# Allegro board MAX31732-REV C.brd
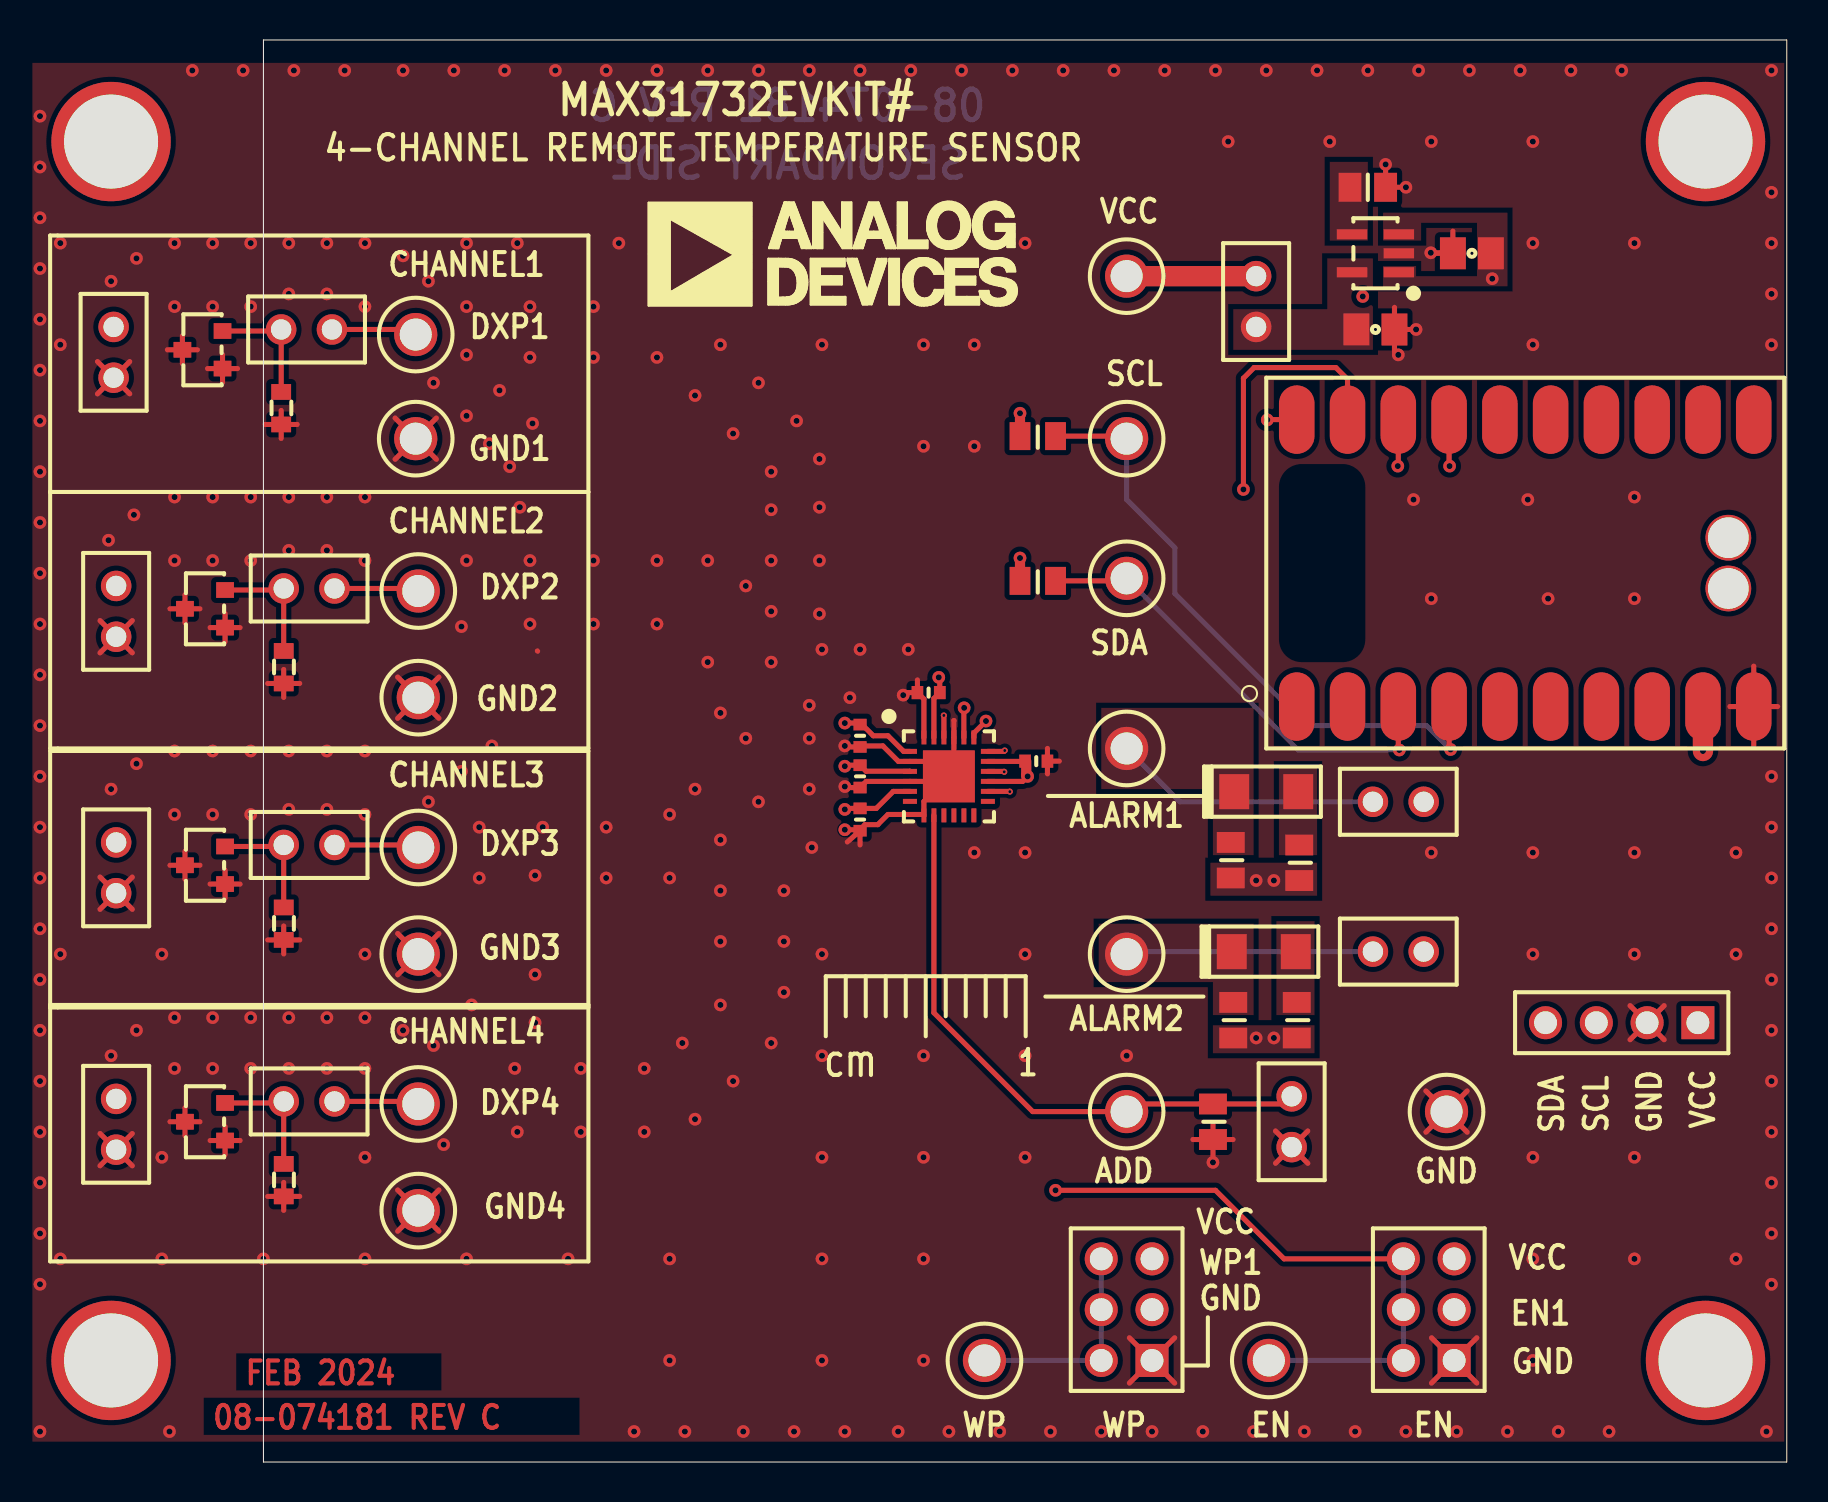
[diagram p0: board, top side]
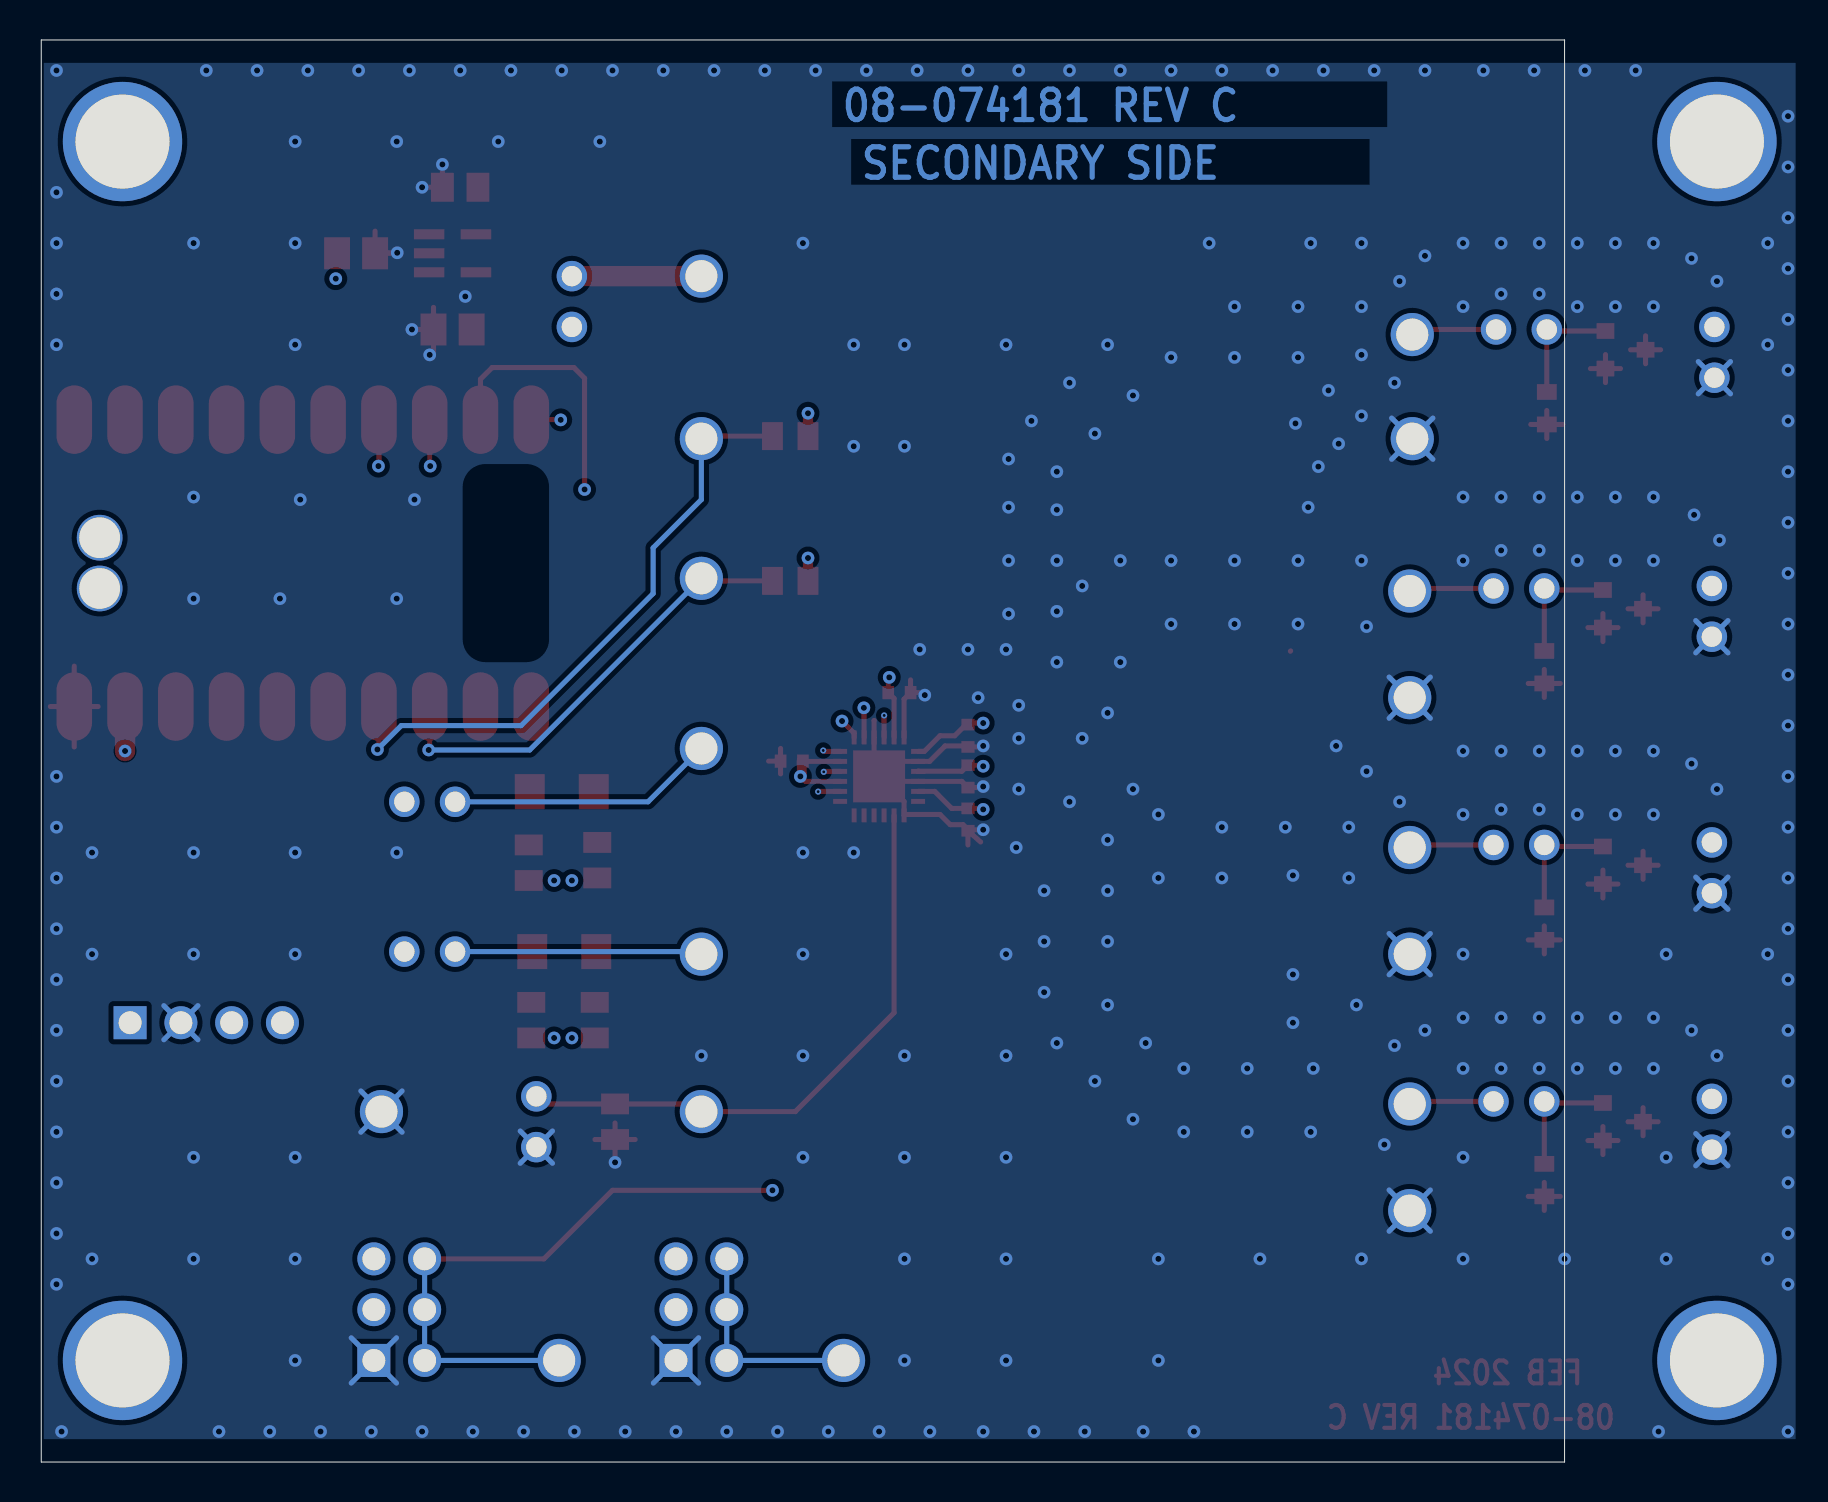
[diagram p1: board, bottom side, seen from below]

Outline 76.2 x 71.12 mm; copper layers: TOP, LAYER_2, LAYER_3, BOTTOM. Coordinates in mm from the lower left corner of the outline.
Outline path: 0,71.12 0,0 76.2,0 76.2,71.12 0,71.12

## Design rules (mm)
constraint set DEFAULT: min track width 0.254

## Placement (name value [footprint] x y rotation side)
C1A  100PF  [C0402]  33.27 38.48 180 top
C1B  100PF  [C0402]  29.85 36.32 270 top
C1C  100PF  [C0402]  29.85 34.29 270 top
C1D  100PF  [C0402]  29.85 32.13 270 top
C2A  TBD0603  [C0603]  0.89 52.7 270 top
C2B  TBD0603  [C0603]  1.02 39.75 270 top
C2C  TBD0603  [C0603]  1.02 26.92 270 top
C2D  TBD0603  [C0603]  1.02 14.1 270 top
C3  0.1uF  [C0402]  38.66 35.05 0 top
C4  0.1UF  [C0805]  55.24 63.75 0 top
C5  1uF  [C0805H60]  60.45 60.45 180 top
C6  1uF  [C0805H60]  55.63 56.64 0 top
DS1  SML-LX1206IW-TR  [LEDSML126W63H43]  50.17 33.53 0 top
DS2  SML-LX1206IW-TR  [LEDSML126W63H43]  50.04 25.53 0 top
H1  PREC004SAAN-RC  [CNTHMHDR1X4L400W100H336]  71.75 21.97 180 top
J1  PEC02SAAN  [CNSULLINSPEC02SAAN]  3.43 56.64 180 top
J2  PEC02SAAN  [CNSULLINSPEC02SAAN]  3.56 43.69 180 top
J3  PEC02SAAN  [CNSULLINSPEC02SAAN]  3.56 30.86 180 top
J4  PEC02SAAN  [CNSULLINSPEC02SAAN]  3.56 18.03 180 top
J5  PEC02SAAN  [CNSULLINSPEC02SAAN]  49.66 59.31 270 top
J6  PEC02SAAN  [CNSULLINSPEC02SAAN]  51.44 18.29 270 top
J7  TSW-103-07-F-D  [CNSAMTEC2X3H330LD36]  44.45 5.08 90 top
J8  TSW-103-07-F-D  [CNSAMTEC2X3H330LD36]  59.56 5.08 90 top
J9  PEC02SAAN  [CNSULLINSPEC02SAAN]  55.5 33.02 0 top
J10  PEC02SAAN  [CNSULLINSPEC02SAAN]  55.5 25.53 0 top
J11  PEC02SAAN  [CNSULLINSPEC02SAAN]  -7.49 56.77 270 top
J12  PEC02SAAN  [CNSULLINSPEC02SAAN]  -7.37 43.81 270 top
J13  PEC02SAAN  [CNSULLINSPEC02SAAN]  -7.37 30.99 270 top
J14  PEC02SAAN  [CNSULLINSPEC02SAAN]  -7.37 18.16 270 top
NOREF  -  []  -12.7 0 90 top
NOREF#2  -  []  275.21 77.85 0 top
NOREF#3  -  []  -60.71 -173.48 0 top
NOREF#4  -  [unnamed#2]  -7.62 5.08 0 top
NOREF#5  -  []  48.69 71.12 0 top
NOREF#6  -  []  76.58 70.48 180 top
NOREF#7  -  []  30.04 19.34 0 top
NOREF#8  -  []  -102.74 -190.75 0 top
NOREF#9  -  []  0.64 70.48 270 top
NOREF#10  -  []  77.22 49.53 0 top
NOREF#11  -  []  343.12 241.69 0 top
NOREF#12  -  []  0.64 0.64 0 top
NOREF#13  -  [unnamed#2]  -7.62 66.04 0 top
NOREF#14  -  []  -12.7 71.12 0 top
NOREF#15  -  []  76.58 0.64 90 top
NOREF#16  -  []  54.99 49.49 0 top
NOREF#17  -  [unnamed#2]  72.14 66.04 0 top
NOREF#18  -  []  37.08 90.21 0 top
NOREF#19  -  []  48.57 49.78 0 top
NOREF#20  -  []  178.18 232.41 0 top
NOREF#21  -  [unnamed#2]  72.14 5.08 0 top
NOREF#22  -  []  350.14 178.18 0 top
Q1  MMBT3906-7-F  [SOT23-M3]  -3.05 55.63 90 top
Q2  MMBT3906-7-F  [SOT23-M3]  -2.92 42.67 90 top
Q3  MMBT3906-7-F  [SOT23-M3]  -2.92 29.84 90 top
Q4  MMBT3906-7-F  [SOT23-M3]  -2.92 17.02 90 top
R1  4.7K  [R0805]  38.73 51.31 180 top
R2  4.7K  [R0805]  38.73 44.07 180 top
R3  15K  [R0805]  47.5 17.02 270 top
R4  4.7K  [R0805]  48.39 30.1 270 top
R5  330  [R0805]  51.82 29.97 270 top
R6  4.7K  [R0805]  48.51 22.1 270 top
R7  330  [R0805]  51.69 22.1 270 top
TP1  WHT  [CNKEY5005-9TP]  7.62 56.39 0 top
TP2  WHT  [CNKEY5005-9TP]  7.62 51.18 0 top
TP3  WHT  [CNKEY5005-9TP]  7.75 43.56 0 top
TP4  WHT  [CNKEY5005-9TP]  7.75 38.23 0 top
TP5  WHT  [CNKEY5005-9TP]  7.75 30.73 0 top
TP6  WHT  [CNKEY5005-9TP]  7.75 25.4 0 top
TP7  WHT  [CNKEY5005-9TP]  7.75 17.91 0 top
TP8  WHT  [CNKEY5005-9TP]  7.75 12.57 0 top
TP9  RED  [CNKEY5005-9TP]  43.18 59.31 0 top
TP10  WHT  [CNKEY5005-9TP]  36.07 5.08 0 top
TP11  WHT  [CNKEY5005-9TP]  50.29 5.08 0 top
TP12  WHT  [CNKEY5005-9TP]  43.18 51.18 0 top
TP13  WHT  [CNKEY5005-9TP]  43.18 44.2 0 top
TP14  WHT  [CNKEY5005-9TP]  43.18 17.53 0 top
TP15  WHT  [CNKEY5005-9TP]  43.18 35.69 0 top
TP16  WHT  [CNKEY5005-9TP]  43.18 25.4 0 top
TP19  BLK  [CNKEY5005-9TP]  59.18 17.53 0 top
U1  MAX31732ATG+  [QFN24_90-0022]  34.29 34.29 270 top
U2  MAX32625PICO#  [MMAX32625PICO_SOCKETED]  63.12 44.96 90 top
U3  LTC1844ES5-3.3#TRMPBF  [TSOT-5]  55.63 60.45 90 top

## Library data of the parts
C1A C1B C1C C1D = CAP: Tolerance: 10; User Part Number: UPN; alternate symbols: (C0402); part number: CAP_SM-100PF,16V,10,E042886,C0402; tolerance: 10
C2A C2B C2C C2D = CAP: User Part Number: UPN; alternate symbols: (C0603); part number: CAP_SM-TBD0603,TBD0603,TBD0603,E000382,C0603
C3 = CAP: Tolerance: 10; User Part Number: UPN; alternate symbols: (C0402); part number: CAP_SM-0.1UF,25V,10,E025751,C0402; tolerance: 10
C4 = CAP: Tolerance: 10; User Part Number: UPN; alternate symbols: (C0805); part number: CAP_SM-0.1UF,25V,10,E059709,C0805; tolerance: 10
C5 C6 = CAP: Tolerance: 10; User Part Number: UPN; alternate symbols: (C0805H60); part number: CAP_SM-1UF,25V,10,E007664,C0805H60; tolerance: 10
DS1 DS2 = DIOLED: Tolerance: N/A; User Part Number: UPN; alternate symbols: (LEDSML126W63H43); part number: DIOLED_SM-SML-LX1206IW-TR,N/A,N/A,E008005,LEDSML126W63H43; tolerance: N/A
H1 = CN4P: User Part Number: UPN; Tolerance: N/A; alternate symbols: (CNTHMHDR1X4L400W100H336); part number: CN4P_TH-PREC004SAAN-RC,E030958,CNTHMHDR1X4L400W100H336; tolerance: N/A
J1-J6 J9-J14 = CN2P: Tolerance: N/A; User Part Number: UPN; alternate symbols: (CNSULLINSPEC02SAAN); part number: CN2P_TH-PEC02SAAN,E011286,CNSULLINSPEC02SAAN; tolerance: N/A
J7 J8 = CN6P_ODD_EVEN: Tolerance: N/A; User Part Number: UPN; alternate symbols: (CNSAMTEC2X3H330LD36); part number: CN6P_ODD_EVEN_TH-TSW-103-07-F-D,E031502,CNSAMTEC2X3H330LD36; tolerance: N/A
Q1-Q4 = TRANPNP_V3: User Part Number: UPN; Tolerance: N/A; alternate symbols: (SOT23-M3); part number: TRANPNP_V3_SM-MMBT3906-7-F,E034958,SOT23-M3; tolerance: N/A
R1 R2 R4 R6 = RES: Tolerance: 0.1; User Part Number: UPN; alternate symbols: (R0805); part number: RES_SM-4.7K,E034780,1/4W,0.1,R0805; tolerance: 0.1
R3 = RES: Tolerance: 0.1; User Part Number: UPN; alternate symbols: (R0805); part number: RES_SM-15K,E003804,1/8W,0.1,R0805; tolerance: 0.1
R5 R7 = RES: Tolerance: 0.1; User Part Number: UPN; alternate symbols: (R0805); part number: RES_SM-330,E025081,1/8W,0.1,R0805; tolerance: 0.1
TP1-TP8 TP10-TP16 = CNTP1P: Tolerance: N/A; User Part Number: UPN; alternate symbols: (CNKEY5005-9TP); part number: CNTP1P_TH-WHT,E025331,CNKEY5005-9TP; tolerance: N/A
TP9 = CNTP1P: Tolerance: N/A; User Part Number: UPN; alternate symbols: (CNKEY5005-9TP); part number: CNTP1P_TH-RED,E019607,CNKEY5005-9TP; tolerance: N/A
TP19 = CNTP1P: Tolerance: N/A; User Part Number: UPN; alternate symbols: (CNKEY5005-9TP); part number: CNTP1P_TH-BLK,E015367,CNKEY5005-9TP; tolerance: N/A
U1 = ADMAX31732_V2: User Part Number: UPN; Tolerance: N/A; alternate symbols: (QFN24_90-0022); part number: ADMAX31732_V2_SM-MAX31732ATG+,E060544,QFN24_90-0022; tolerance: N/A
U2 = MOD_MAX32625: User Part Number: UPN; Tolerance: N/A; alternate symbols: (MODMAX32625PICO_20P); part number: MOD_MAX32625_TH-MAX32625PICO#,E060564,MMAX32625PICO_SOCKETED; tolerance: N/A
U3 = LINLTC1844: User Part Number: UPN; Tolerance: N/A; alternate symbols: (TSOT-5); part number: LINLTC1844_SM-LTC1844ES5-3.3#TRMPBF,E034094,TSOT-5; tolerance: N/A

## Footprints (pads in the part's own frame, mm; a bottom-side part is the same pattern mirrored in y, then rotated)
C0402
  rect 0.584x0.66 smd: 1(-0.559,0) 2(0.559,0)
C0603
  rect 0.787x0.991 smd: 1(-0.813,0) 2(0.813,0)
C0805
  rect 1.143x1.448 smd: 1(-0.889,0) 2(0.889,0)
C0805H60
  rect 1.295x1.6 smd: 1(-0.953,0) 2(0.953,0)
CNKEY5005-9TP
  round 2.159 hole 1.6: 1(0,0)
CNSAMTEC2X3H330LD36
  rect 1.651x1.651 hole 1.143: 1(0,0)
  round 1.651 hole 1.143: 2(0,2.54) 3(2.54,0) 4(2.54,2.54) 5(5.08,0) 6(5.08,2.54)
CNSULLINSPEC02SAAN
  round 1.524 hole 1.016: 1(0,0) 2(2.54,0)
CNTHMHDR1X4L400W100H336
  rect 1.651x1.651 hole 1.143: 1(0,0)
  round 1.651 hole 1.143: 2(2.54,0) 3(5.08,0) 4(7.62,0)
LEDSML126W63H43
  rect 1.499x1.753 smd: A(1.6,0) C(-1.6,0)
MMAX32625PICO_SOCKETED
  round 2.286 hole 2.032 unplated: (-1.27,-10.16) (1.27,-10.16)
  rrect 3.429x1.778 smd: 1(-7.176,11.43) 2(-7.176,8.89) 3(-7.176,6.35) 4(-7.176,3.81) 5(-7.176,1.27) 6(-7.176,-1.27) 7(-7.176,-3.81) 8(-7.176,-6.35) 9(-7.176,-8.89) 10(-7.176,-11.43) 11(7.176,-11.43) 12(7.176,-8.89) 13(7.176,-6.35) 14(7.176,-3.81) 15(7.176,-1.27) 16(7.176,1.27) 17(7.176,3.81) 18(7.176,6.35) 19(7.176,8.89) 20(7.176,11.43)
QFN24_90-0022
  rect 0.25x0.7 smd: 1(-1.25,-1.95) 2(-0.75,-1.95) 3(-0.25,-1.95) 4(0.25,-1.95) 5(0.75,-1.95) 6(1.25,-1.95) 13(1.25,1.95) 14(0.75,1.95) 15(0.25,1.95) 16(-0.25,1.95) 17(-0.75,1.95) 18(-1.25,1.95)
  rect 0.7x0.25 smd: 7(1.95,-1.25) 8(1.95,-0.75) 9(1.95,-0.25) 10(1.95,0.25) 11(1.95,0.75) 12(1.95,1.25) 19(-1.95,1.25) 20(-1.95,0.75) 21(-1.95,0.25) 22(-1.95,-0.25) 23(-1.95,-0.75) 24(-1.95,-1.25)
  rect 2.6x2.6 smd: 25(0,0)
R0805
  rect 1.041x1.397 smd: 1(-0.889,0) 2(0.889,0)
SOT23-M3
  rect 0.787x0.889 smd: 1(-0.94,-1.003) 2(0.94,-1.003) 3(0,1.003)
TSOT-5
  rect 0.508x1.524 smd: 1(-0.95,-1.17) 2(0,-1.17) 3(0.95,-1.17) 4(0.95,1.17) 5(-0.95,1.17)
unnamed#2
  round 5.969 hole 4.699 unplated: (0,0)

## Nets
3.3V: C6.1 J5.2(N2) U3.5
+5V: C5.1 U2.9 U3.1 U3.3(SHDN_N)
GND_SIGNAL: C1A.2(N2) C1B.2(N2) C1C.2(N2) C1D.2(N2) C2A.2(N2) C2B.2(N2) C2C.2(N2) C2D.2(N2) C3.2(N2) C4.2(N2) C5.2(N2) C6.2(N2) H1.2 J6.2(N2) J7.1 J8.1 J11.2(N2) J12.2(N2) J13.2(N2) J14.2(N2) Q1.1 Q1.3 Q2.1 Q2.3 Q3.1 Q3.3 Q4.1 Q4.3 R3.2(N2) TP2.1(N1) TP4.1(N1) TP6.1(N1) TP8.1(N1) TP19.1(N1) U1.2 U1.4 U1.7 U1.21 U1.24 U1.25 U2.10 U3.2
VCC: C3.1 H1.1 J5.1 J7.5 J8.5 R1.2(N2) R2.2(N2) R4.2(N2) R5.2(N2) R6.2(N2) R7.2(N2) TP9.1(N1) U1.15 U1.17
ADD: J6.1 R3.1 TP14.1(N1) U1.8
AL1: J9.2(N2) U2.18
AL2: J10.2(N2) U2.17
DXP1: C1A.1 J1.1 J11.1 TP1.1(N1) U1.23
DXP2: C1B.1 J2.1 J12.1 TP3.1(N1) U1.1
DXP3: C1C.1 J3.1 J13.1 TP5.1(N1) U1.3
DXP4: C1D.1 J4.1 J14.1 TP7.1(N1) U1.5
EN: J8.2 J8.4 J8.6(N6) TP11.1(N1) U1.14
EN1: J8.3 U2.19
SCL: H1.3 R1.1 TP12.1(N1) U1.20 U2.4
SDA: H1.4(N4) R2.1 TP13.1(N1) U1.19 U2.3
UNNAMED_2_ADMAX31732V2_I178_ALARM1: DS1.C J9.1 R4.1 TP15.1(N1) U1.18
UNNAMED_2_ADMAX31732V2_I178_ALARM2: DS2.C J10.1 R6.1 TP16.1(N1) U1.16
UNNAMED_2_CAP_I100_N1: C4.1 U3.4
UNNAMED_2_CAP_I132_N1: C2B.1 J2.2(N2) Q2.2(E)
UNNAMED_2_CAP_I145_N1: C2C.1 J3.2(N2) Q3.2(E)
UNNAMED_2_CAP_I151_N1: C2D.1 J4.2(N2) Q4.2(E)
UNNAMED_2_CN2P_I126_N2: C2A.1 J1.2(N2) Q1.2(E)
UNNAMED_2_DIOLED_I82_P: DS1.A(P) R5.1
UNNAMED_2_DIOLED_I87_P: DS2.A(P) R7.1
WP: J7.2 J7.4 J7.6(N6) TP10.1(N1) U1.22(WP)
WP1: J7.3 U2.20

Pads without a net: U1 6 9 10 11 12 13; U2 1 2 5 6 7 8 11 12 13 14 15 16

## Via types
v1: diameter 0.635, hole 0.305, TOP to BOTTOM, 333 vias
v2: diameter 0.305, hole 0.152, TOP to BOTTOM, 4 vias

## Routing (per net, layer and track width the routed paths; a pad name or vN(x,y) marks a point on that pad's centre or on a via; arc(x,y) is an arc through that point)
+5V: length 57.8
  TOP w1.016: U2.9 v1(72.01,35.56)
  LAYER_2 w1.016: v1(72.01,35.56) 70.1,37.47 49.15,37.47 47.12,39.5 47.12,50.67 52.2,55.75 54.23,55.75 57.28,58.8 61.09,58.8 v1(61.47,59.18)
GND_SIGNAL: length 326
  TOP w0.254: 43.32,3.95 J7.1 ; J7.1 45.58,3.95 ; J7.1 43.32,6.21 ; J7.1 45.58,6.21 ; 13.7,40.56 13.72,40.55 ; 34.54,37.08 34.54,37.08 U1.21 34.54,34.54 ; TP6.1 8.78,24.37 ; TP6.1 6.72,24.37 ; TP6.1 8.78,26.43 ; TP6.1 6.72,26.43 ; 46.49,16.13 R3.2 ; R3.2 47.5,16.96 ; R3.2 47.5,15.3 ; R3.2 48.5,16.13 ; Q1.3 -4.05,56.33 ; Q1.3 -4.8,55.63 ; Q1.3 -4.05,54.93 ; Q1.3 -3.3,55.63 ; Q3.3 -3.92,30.54 ; Q3.3 -3.17,29.84 ; Q3.3 -3.92,29.15 ; Q3.3 -4.67,29.84 ; C3.2 39.82,35.05 ; C3.2 39.22,34.42 ; C3.2 39.22,35.69 ; 6.72,37.2 TP4.1 ; TP4.1 8.78,37.2 ; TP4.1 6.72,39.26 ; TP4.1 8.78,39.26 ; 68.36,21.12 69.22,21.97 ; 69.22,21.97 68.36,22.82 ; 69.22,21.97 70.07,22.82 ; 69.22,21.97 70.07,21.12 ; Q2.1 -1.17,41.73 ; Q2.1 -1.92,42.43 ; Q2.1 -2.67,41.73 ; Q2.1 -1.92,41.03 ; Q2.3 -3.17,42.67 ; Q2.3 -3.92,41.97 ; Q2.3 -3.92,43.37 ; Q2.3 -4.67,42.67 ; 0.09,51.89 C2A.2 ; C2A.2 0.89,51.19 ; C2A.2 1.69,51.89 ; C2A.2 0.89,52.59 ; 58.15,18.56 TP19.1 ; TP19.1 58.15,16.5 ; TP19.1 60.21,18.56 ; TP19.1 60.21,16.5 ; 74.55,35.76 U2.10 ; U2.10 74.55,39.8 ; U2.10 73.35,37.78 ; U2.10 75.74,37.78 ; -7.37,15.62 -6.56,16.43 ; -7.37,15.62 -8.17,16.43 ; -7.37,15.62 -8.17,14.82 ; -7.37,15.62 -6.56,14.82 ; -4.67,17.02 Q4.3 ; Q4.3 -3.92,17.72 ; Q4.3 -3.92,16.32 ; Q4.3 -3.17,17.02 ; C2B.2 1.82,38.94 ; C2B.2 1.02,38.24 ; C2B.2 0.22,38.94 ; C2B.2 1.02,39.64 ; -1.92,28.21 Q3.1 ; Q3.1 -2.67,28.91 ; Q3.1 -1.92,29.6 ; Q3.1 -1.17,28.91 ; -2.04,53.99 Q1.1 ; Q1.1 -2.04,55.39 ; Q1.1 -2.79,54.69 ; Q1.1 -1.29,54.69 ; J6.2 52.24,16.55 ; J6.2 50.63,14.94 ; J6.2 52.24,14.94 ; J6.2 50.63,16.55 ; TP2.1 8.65,50.15 ; TP2.1 8.65,52.21 ; TP2.1 6.59,52.21 ; TP2.1 6.59,50.15 ; 29.21,33.73 C1C.2 30.15,34.04 U1.4 34.04,34.04 33.04,33.04 U1.7 33,32.38 31.24,32.38 30.73,31.88 30.09,31.88 29.84,31.62 v1(29.08,31.62) ; 6.72,11.54 TP8.1 ; TP8.1 6.72,13.6 ; TP8.1 8.78,11.54 ; TP8.1 8.78,13.6 ; v1(58.39,60.48) 59.47,60.48 C5.2 ; 58.43,6.21 J8.1 ; J8.1 60.69,6.21 ; J8.1 60.69,3.95 ; J8.1 58.43,3.95 ; C2D.2 1.02,13.98 ; C2D.2 1.82,13.28 ; C2D.2 0.22,13.28 ; C2D.2 1.02,12.59 ; C2C.2 1.82,26.11 ; C2C.2 0.22,26.11 ; C2C.2 1.02,26.81 ; C2C.2 1.02,25.41 ; -8.17,42.08 J12.2 ; J12.2 -8.17,40.47 ; J12.2 -6.56,42.08 ; J12.2 -6.56,40.47 ; Q4.1 -1.92,16.78 ; Q4.1 -1.92,15.38 ; Q4.1 -2.67,16.08 ; Q4.1 -1.17,16.08 ; 29.85,35.82 29.85,35.81 30.99,35.81 31.76,35.04 U1.2 33.54,35.04 ; J11.2 -6.69,55.03 ; J11.2 -8.3,55.03 ; J11.2 -8.3,53.42 ; J11.2 -6.69,53.42 ; J13.2 -6.56,27.64 ; J13.2 -6.56,29.25 ; J13.2 -8.17,27.64 ; J13.2 -8.17,29.25 ; 32.12,38.48 C1A.2 ; C1A.2 33.04,38.16 U1.24 ; C1A.2 32.72,39.12 ; 29.21,35.76 C1B.2 ; 58.55,60.45 C5.2 ; C5.2 59.5,61.56 ; 56.58,55.54 C6.2 ; C6.2 56.58,57.75 ; C6.2 57.53,56.64 ; 57.01,63.75 C4.2 56.13,64.78 ; 29.85,30.86 C1D.2 29.21,31.01
  LAYER_2 w0.254: 6.72,24.37 TP6.1 ; TP6.1 8.78,26.43 ; TP6.1 6.72,26.43 ; TP6.1 8.78,24.37 ; -7.37,15.62 -6.56,16.43 ; -7.37,15.62 -6.56,14.82 ; -7.37,15.62 -8.17,14.82 ; -7.37,15.62 -8.17,16.43 ; TP8.1 8.78,13.6 ; TP8.1 8.78,11.54 ; TP8.1 6.72,11.54 ; TP8.1 6.72,13.6 ; -8.17,27.64 J13.2 ; J13.2 -8.17,29.25 ; J13.2 -6.56,27.64 ; J13.2 -6.56,29.25 ; TP4.1 8.78,39.26 ; TP4.1 6.72,39.26 ; TP4.1 6.72,37.2 ; TP4.1 8.78,37.2 ; 6.59,52.21 TP2.1 ; TP2.1 8.65,50.15 ; TP2.1 8.65,52.21 ; TP2.1 6.59,50.15 ; -8.3,53.42 J11.2 ; J11.2 -6.69,55.03 ; J11.2 -6.69,53.42 ; J11.2 -8.3,55.03 ; -8.17,40.47 J12.2 ; J12.2 -6.56,42.08 ; J12.2 -6.56,40.47 ; J12.2 -8.17,42.08
  LAYER_3 w0.254: TP6.1 8.78,24.37 ; TP6.1 8.78,26.43 ; TP6.1 6.72,26.43 ; TP6.1 6.72,24.37 ; 6.59,50.15 TP2.1 ; TP2.1 6.59,52.21 ; TP2.1 8.65,52.21 ; TP2.1 8.65,50.15 ; -8.17,16.43 -7.37,15.62 ; -7.37,15.62 -6.56,14.82 ; -7.37,15.62 -6.56,16.43 ; -7.37,15.62 -8.17,14.82 ; 58.15,16.5 TP19.1 ; TP19.1 58.15,18.56 ; TP19.1 60.21,16.5 ; TP19.1 60.21,18.56 ; J6.2 52.24,16.55 ; J6.2 50.63,14.94 ; J6.2 50.63,16.55 ; J6.2 52.24,14.94 ; 6.72,39.26 TP4.1 ; TP4.1 8.78,37.2 ; TP4.1 8.78,39.26 ; TP4.1 6.72,37.2 ; -8.17,42.08 J12.2 ; J12.2 -6.56,40.47 ; J12.2 -8.17,40.47 ; J12.2 -6.56,42.08 ; J8.1 60.41,5.93 ; J8.1 60.41,4.23 ; J8.1 58.71,4.23 ; J8.1 58.71,5.93 ; -8.3,55.03 J11.2 ; J11.2 -6.69,53.42 ; J11.2 -8.3,53.42 ; J11.2 -6.69,55.03 ; -8.17,27.64 J13.2 ; J13.2 -6.56,29.25 ; J13.2 -8.17,29.25 ; J13.2 -6.56,27.64 ; 68.36,22.82 69.22,21.97 ; 69.22,21.97 70.07,22.82 ; 69.22,21.97 70.07,21.12 ; 69.22,21.97 68.36,21.12 ; TP8.1 8.78,13.6 ; TP8.1 6.72,11.54 ; TP8.1 8.78,11.54 ; TP8.1 6.72,13.6 ; 43.6,5.93 J7.1 ; J7.1 45.3,4.23 ; J7.1 43.6,4.23 ; J7.1 45.3,5.93
  BOTTOM w0.254: 50.63,14.94 J6.2 ; J6.2 52.24,14.94 ; J6.2 52.24,16.55 ; J6.2 50.63,16.55 ; 6.59,50.15 TP2.1 ; TP2.1 8.65,52.21 ; TP2.1 8.65,50.15 ; TP2.1 6.59,52.21 ; -8.17,14.82 -7.37,15.62 ; -7.37,15.62 -8.17,16.43 ; -7.37,15.62 -6.56,16.43 ; -7.37,15.62 -6.56,14.82 ; -8.3,53.42 J11.2 ; J11.2 -6.69,55.03 ; J11.2 -8.3,55.03 ; J11.2 -6.69,53.42 ; 68.36,22.82 69.22,21.97 ; 69.22,21.97 70.07,22.82 ; 69.22,21.97 68.36,21.12 ; 69.22,21.97 70.07,21.12 ; 6.72,13.6 TP8.1 ; TP8.1 6.72,11.54 ; TP8.1 8.78,11.54 ; TP8.1 8.78,13.6 ; 58.15,16.5 TP19.1 ; TP19.1 58.15,18.56 ; TP19.1 60.21,16.5 ; TP19.1 60.21,18.56 ; -8.17,42.08 J12.2 ; J12.2 -8.17,40.47 ; J12.2 -6.56,40.47 ; J12.2 -6.56,42.08 ; -8.17,27.64 J13.2 ; J13.2 -8.17,29.25 ; J13.2 -6.56,29.25 ; J13.2 -6.56,27.64 ; 58.43,6.21 J8.1 ; J8.1 60.69,3.95 ; J8.1 58.43,3.95 ; J8.1 60.69,6.21 ; TP4.1 8.78,39.26 ; TP4.1 6.72,39.26 ; TP4.1 6.72,37.2 ; TP4.1 8.78,37.2 ; 43.32,3.95 J7.1 ; J7.1 43.32,6.21 ; J7.1 45.58,3.95 ; J7.1 45.58,6.21 ; 6.72,26.43 TP6.1 ; TP6.1 8.78,26.43 ; TP6.1 8.78,24.37 ; TP6.1 6.72,24.37
  vias: v1(-11.18,67.31) v1(-11.18,64.77) v1(-11.18,62.23) v1(-11.18,59.69) v1(-11.18,57.15) v1(-11.18,54.61) v1(-11.18,52.07) v1(-11.18,49.53) v1(-11.18,46.99) v1(-11.18,44.45) v1(-11.18,41.91) v1(-11.18,39.37) v1(-11.18,36.83) v1(-11.18,34.29) v1(-11.18,31.75) v1(-11.18,29.21) v1(-11.18,26.67) v1(-11.18,24.13) v1(-11.18,21.59) v1(-11.18,19.05) v1(-11.18,16.51) v1(-11.18,13.97) v1(-11.18,11.43) v1(-11.18,8.89) v1(-11.18,1.52) v1(-10.16,60.96) v1(-10.16,55.88) v1(-10.16,25.4) v1(-10.16,10.16) v1(-7.75,46.1) v1(-7.62,59.05) v1(-7.62,33.66) v1(-7.62,20.32) v1(-6.48,47.37) v1(-6.35,60.2) v1(-6.35,34.92) v1(-6.35,21.59) v1(-5.08,25.4) v1(-5.08,15.24) v1(-5.08,10.16) v1(-4.7,1.52) v1(-4.44,60.96) v1(-4.44,57.78) v1(-4.44,48.26) v1(-4.44,45.09) v1(-4.44,35.56) v1(-4.44,32.38) v1(-4.44,22.23) v1(-4.44,19.68) v1(-3.56,69.6) v1(-2.54,60.96) v1(-2.54,57.78) v1(-2.54,48.26) v1(-2.54,45.09) v1(-2.54,35.56) v1(-2.54,32.38) v1(-2.54,22.23) v1(-2.54,19.68) v1(-1.02,69.6) v1(-0.63,60.96) v1(-0.63,57.78) v1(-0.63,48.26) v1(-0.63,45.09) v1(-0.63,35.56) v1(-0.63,32.38) v1(-0.63,22.23) v1(-0.63,19.68) v1(0,10.16) v1(1.27,60.96) v1(1.27,58.42) v1(1.27,48.26) v1(1.27,45.59) v1(1.27,35.56) v1(1.27,32.64) v1(1.27,22.23) v1(1.27,19.68) v1(1.52,69.6) v1(3.18,60.96) v1(3.18,58.42) v1(3.18,48.26) v1(3.18,45.59) v1(3.18,35.56) v1(3.18,32.64) v1(3.18,22.23) v1(3.18,19.68) v1(4.06,69.6) v1(5.08,60.96) v1(5.08,57.78) v1(5.08,48.26) v1(5.08,45.09) v1(5.08,35.56) v1(5.08,32.38) v1(5.08,25.4) v1(5.08,22.23) v1(5.08,19.68) v1(5.08,15.24) v1(5.08,10.16) v1(6.98,69.6) v1(6.98,60.33) v1(6.98,21.59) v1(8.25,59.05) v1(8.25,33.02) v1(8.51,53.98) v1(8.51,20.83) v1(9.02,15.88) v1(9.53,69.6) v1(9.91,41.78) v1(9.91,34.54) v1(10.16,60.96) v1(10.16,57.78) v1(10.16,55.37) v1(10.16,52.32) v1(10.16,45.09) v1(10.16,10.16) v1(10.41,22.86) v1(10.8,31.75) v1(10.8,29.21) v1(11.3,50.93) v1(11.43,35.81) v1(11.81,53.59) v1(12.07,69.6) v1(12.32,49.78) v1(12.57,19.68) v1(12.7,60.96) v1(12.7,16.51) v1(12.83,47.75) v1(13.34,57.78) v1(13.34,55.24) v1(13.34,45.09) v1(13.34,41.91) v1(13.46,51.94) v1(13.59,29.34) v1(13.59,24.38) v1(13.59,21.97) v1(13.97,31.75) v1(14.61,69.6) v1(15.24,10.16) v1(15.88,19.68) v1(15.88,16.51) v1(16.51,57.78) v1(16.51,55.24) v1(16.51,45.09) v1(16.51,41.91) v1(17.14,69.6) v1(17.14,31.75) v1(17.14,29.21) v1(17.78,60.96) v1(18.54,1.52) v1(19.05,19.68) v1(19.05,16.51) v1(19.68,69.6) v1(19.68,55.24) v1(19.68,45.09) v1(19.68,41.91) v1(20.32,32.38) v1(20.32,29.21) v1(20.32,10.16) v1(20.32,5.08) v1(20.96,20.95) v1(21.08,1.52) v1(21.59,53.34) v1(21.59,33.66) v1(21.59,17.14) v1(22.22,69.6) v1(22.22,45.09) v1(22.22,40.01) v1(22.86,55.88) v1(22.86,37.47) v1(22.86,31.11) v1(22.86,28.57) v1(22.86,26.04) v1(22.86,22.86) v1(23.5,51.44) v1(23.5,19.05) v1(24,1.52) v1(24.13,43.81) v1(24.13,36.2) v1(24.77,69.6) v1(24.77,53.98) v1(24.77,33.02) v1(25.4,49.53) v1(25.4,47.62) v1(25.4,45.09) v1(25.4,42.55) v1(25.4,40.01) v1(25.4,20.95) v1(26.04,28.57) v1(26.04,26.04) v1(26.04,23.5) v1(26.54,1.52) v1(26.67,52.07) v1(27.31,69.6) v1(27.31,37.85) v1(27.31,36.2) v1(27.31,33.66) v1(27.43,30.73) v1(27.81,50.16) v1(27.81,47.75) v1(27.81,45.09) v1(27.81,42.42) v1(27.94,55.88) v1(27.94,40.64) v1(27.94,25.4) v1(27.94,20.32) v1(27.94,15.24) v1(27.94,10.16) v1(27.94,5.08) v1(29.08,35.81) v1(29.08,33.78) v1(29.08,1.52) v1(29.34,38.23) v1(29.85,69.6) v1(29.85,40.64) v1(31.75,1.52) v1(32,38.35) v1(32.26,40.64) v1(32.39,69.6) v1(33.02,55.88) v1(33.02,50.8) v1(33.02,20.32) v1(33.02,15.24) v1(33.02,10.16) v1(33.02,5.08) v1(34.29,1.52) v1(34.92,69.6) v1(35.56,55.88) v1(35.56,50.8) v1(35.56,30.48) v1(36.83,1.52) v1(37.47,69.6) v1(38.1,60.96) v1(38.1,30.48) v1(38.1,25.4) v1(38.1,20.32) v1(38.1,15.24) v1(39.37,1.52) v1(40,69.6) v1(41.91,1.52) v1(42.55,69.6) v1(43.18,20.32) v1(44.45,1.52) v1(45.08,69.6) v1(46.99,1.52) v1(47.5,14.99) v1(47.62,69.6) v1(48.26,66.04) v1(49.53,1.52) v1(50.17,69.6) v1(52.07,1.52) v1(52.7,69.6) v1(53.34,66.04) v1(54.61,1.52) v1(54.99,58.29) v1(55.24,69.6) v1(56.13,64.9) v1(56.77,55.37) v1(57.15,63.75) v1(57.15,1.52) v1(57.53,48.13) v1(57.66,56.64) v1(57.78,69.6) v1(58.42,66.04) v1(58.42,43.18) v1(58.42,30.48) v1(59.69,1.52) v1(60.33,69.6) v1(62.23,1.52) v1(62.86,69.6) v1(63.25,48.13) v1(63.5,66.04) v1(63.5,60.96) v1(63.5,55.88) v1(63.5,30.48) v1(63.5,25.4) v1(63.5,15.24) v1(63.5,10.16) v1(63.5,5.08) v1(64.26,43.18) v1(64.77,1.52) v1(65.41,69.6) v1(67.31,1.52) v1(67.94,69.6) v1(68.58,60.96) v1(68.58,48.26) v1(68.58,43.18) v1(68.58,30.48) v1(68.58,25.4) v1(68.58,15.24) v1(68.58,10.16) v1(73.66,30.48) v1(73.66,25.4) v1(73.66,10.16) v1(75.18,1.52) v1(75.44,69.6) v1(75.44,63.5) v1(75.44,60.96) v1(75.44,58.42) v1(75.44,55.88) v1(75.44,34.29) v1(75.44,31.75) v1(75.44,29.21) v1(75.44,26.67) v1(75.44,24.13) v1(75.44,21.59) v1(75.44,19.05) v1(75.44,16.51) v1(75.44,13.97) v1(75.44,11.43) v1(75.44,8.89)
VCC: length 13.8
  TOP w0.254: U1.17 38.09,35.04 C3.1 38.16,35.05 38.15,35.04 ; U1.15 37.98,34.04 v1(38.23,34.29)
  TOP w0.508: 38.16,35.05 38.16,34.36 v1(38.23,34.29) 38.23,34.29 ; R1.2 v1(37.85,52.45) ; R2.2 v1(37.85,45.21)
  TOP w1.016: J5.1 TP9.1
  LAYER_3 w0.254: 43.05,59.18 TP9.1
  vias: v1(49.66,29.08) v1(49.66,21.21) v1(50.55,29.08) v1(50.55,21.21)
ADD: length 30.3
  TOP w0.254: J6.1 51.05,17.91 R3.1 43.56,17.91 TP14.1 ; TP14.1 43.18,17.65 ; TP14.1 38.48,17.53 33.54,22.47 U1.8
AL1: length 27.7
  TOP w0.254: v1(56.74,49.81) 56.77,49.83 56.77,52.13
  LAYER_3 w0.254: v1(56.74,49.81) 57.25,49.81 59.44,47.62 61.98,47.62 63.12,46.48 63.12,34.67 61.47,33.02 J9.2
AL2: length 37
  TOP w0.254: v1(59.33,49.81) 59.31,49.83 U2.17
  LAYER_3 w0.254: v1(59.33,49.81) 59.61,49.53 63.37,49.53 65.66,47.24 65.66,29.08 62.1,25.53 J10.2
DXP1: length 65.1
  TOP w0.254: TP1.1 7.37,56.64 J1.1 ; v1(33.78,39.24) 33.83,39.19 C1A.1 33.54,38.19 U1.23
  LAYER_2 w0.254: v1(33.78,39.24) 27.69,39.24 26.67,40.26 26.67,50.04 20.32,56.39 TP1.1
  LAYER_3 w0.254: 7.62,57.28 5.59,59.31 -4.95,59.31 J11.1 ; 7.62,57.28 7.75,57.15 7.75,56.52 ; 7.62,57.28 TP1.1
DXP2: length 52.4
  TOP w0.254: U1.1 32.02,35.54 31.24,36.32 30.51,36.32 29.95,36.88 C1B.1 29.77,36.96 v1(29.08,36.96) ; TP3.1 7.62,43.69 J2.1
  LAYER_2 w0.254: v1(29.08,36.96) 25.02,36.96 23.75,38.23 23.75,41.66 21.84,43.56 TP3.1
  LAYER_3 w0.254: J12.1 -7.37,44.2 -4.95,46.61 5.59,46.61 7.75,44.45 TP3.1
DXP3: length 48.4
  TOP w0.254: TP5.1 7.62,30.86 J3.1 ; v1(29.08,34.8) 29.13,34.85 C1C.1 30.15,34.55 32.33,34.55 U1.3 32.33,34.54
  LAYER_2 w0.254: v1(29.08,34.8) 24.89,34.8 20.83,30.73 TP5.1
  LAYER_3 w0.254: J13.1 -7.37,31.11 -4.95,33.53 5.59,33.53 7.75,31.37 TP5.1
DXP4: length 57.8
  TOP w0.254: TP7.1 7.62,18.03 J4.1 ; U1.5 31.51,33.54 30.66,32.69 C1D.1 29.13,32.69 v1(29.08,32.64)
  LAYER_2 w0.254: TP7.1 20.45,17.91 24.64,22.1 24.64,29.72 27.56,32.64 v1(29.08,32.64)
  LAYER_3 w0.254: J14.1 -7.37,18.41 -4.95,20.83 5.56,20.83 7.75,18.64 TP7.1
EN: length 52.7
  TOP w0.254: v2(37.34,33.53) 37.33,33.54 U1.14 ; J8.6 51.05,10.16 47.62,13.59 v1(39.62,13.59)
  LAYER_3 w0.254: v2(37.34,33.53) 37.47,33.53 39.5,31.5 39.5,13.72 v1(39.62,13.59)
  BOTTOM w0.254: TP11.1 J8.2 J8.4 J8.6
EN1: length 68.4
  TOP w0.254: v1(49.02,48.64) 49.02,54.2 49.56,54.74 53.64,54.74 54.23,54.15 U2.19
  LAYER_3 w0.254: J8.3 61.21,7.62 62.23,8.64 62.23,11.68 61.21,12.7 51.69,12.7 48.77,15.62 48.77,35.31 47.75,36.32 47.75,47.37 v1(49.02,48.64)
SCL: length 86.8
  TOP w0.254: U2.4 59.31,35.71 v1(59.39,35.64) ; U1.20 35.04,37.71 v1(35.05,37.72) ; R1.1 43.05,51.31 TP12.1
  LAYER_3 w0.254: H1.3 66.67,22.99 65.91,23.75 63.12,23.75 61.98,22.61 54.74,22.61 52.58,24.77 52.58,34.29 53.09,34.8 58.55,34.8 v1(59.39,35.64) ; TP12.1 43.18,49.15 42.55,48.51 37.08,48.51 35.05,46.48 v1(35.05,37.72)
  BOTTOM w0.254: v1(59.39,35.64) 58.19,36.83 52.2,36.83 45.59,43.43 45.59,45.72 43.18,48.13 TP12.1
SDA: length 72
  TOP w0.254: U1.19 35.54,36.45 v1(36.14,37.06) ; TP13.1 43.05,44.07 R2.1 ; v1(56.82,35.61) 56.77,35.66 56.77,37.78
  LAYER_3 w0.254: TP13.1 43.18,46.61 42.42,47.37 37.59,47.37 36.26,46.04 36.26,37.17 v1(36.14,37.06) ; H1.4 54.36,21.97 51.94,24.38 51.94,34.67 52.88,35.61 v1(56.82,35.61)
  BOTTOM w0.254: TP13.1 51.77,35.61 v1(56.82,35.61)
UNNAMED_2_ADMAX31732V2_I178_ALARM1: length 20.4
  TOP w0.254: v2(37.08,35.59) 37.04,35.54 U1.18
  LAYER_2 w0.254: TP15.1 43.08,35.59 v2(37.08,35.59)
  BOTTOM w0.254: J9.1 45.85,33.02 TP15.1
UNNAMED_2_ADMAX31732V2_I178_ALARM2: length 27.5
  TOP w0.254: TP16.1 43.05,25.27 ; v2(37.06,34.52) 37.04,34.54 U1.16
  LAYER_3 w0.254: TP16.1 43.18,31.62 39.62,35.18 37.72,35.18 v2(37.06,34.52)
  BOTTOM w0.254: TP16.1 43.31,25.53 J10.1
UNNAMED_2_CAP_I132_N1: length 6.1
  TOP w0.254: Q2.2 0.94,43.61 J2.2 C2B.1
UNNAMED_2_CAP_I145_N1: length 6.1
  TOP w0.254: C2C.1 J3.2 0.94,30.78 Q3.2
UNNAMED_2_CAP_I151_N1: length 6.1
  TOP w0.254: Q4.2 0.94,17.96 J4.2 C2D.1
UNNAMED_2_CN2P_I126_N2: length 6.1
  TOP w0.254: Q1.2 0.81,56.57 0.89,56.64 C2A.1 0.9,53.51
WP: length 50.4
  TOP w0.254: U1.22 34.04,37.33 v2(34.04,37.34)
  LAYER_3 w0.254: v2(34.04,37.34) 31.37,37.34 30.48,36.45 30.48,15.75 36.07,10.16 J7.6
  BOTTOM w0.254: TP10.1 J7.2 J7.4 J7.6
WP1: length 49.2
  TOP w0.254: 51.69,52.13 50.23,52.13 v1(50.22,52.12)
  LAYER_3 w0.254: v1(50.22,52.12) 46.74,48.64 46.74,8.51 45.85,7.62 J7.3

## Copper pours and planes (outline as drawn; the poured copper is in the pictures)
3.3V on TOP: 48.51,57.66 48.51,55.63 55.5,55.63 55.5,60.2 53.21,60.2 53.21,57.66
+5V on TOP: 56.01,61.09 56.01,62.48 62.23,62.48 62.23,58.8 56.01,58.8 56.01,59.82 57.66,59.82 57.66,59.31 60.71,59.31 60.71,61.98 57.91,61.98 57.91,61.09
GND_SIGNAL on TOP: 32.99,35.59 32.99,32.99 35.59,32.99 35.59,35.59
GND_SIGNAL on TOP: -11.56,69.98 76.07,69.98 76.07,1.02 -11.56,1.02 ; 1 cut-out
GND_SIGNAL on BOTTOM: -11.56,69.98 76.07,69.98 76.07,1.14 -11.56,1.14
GND_SIGNAL on LAYER_2, LAYER_3: -11.68,69.98 76.07,69.98 76.07,1.02 -11.68,1.02
VCC on TOP: 47.37,29.97 47.37,28.32 52.7,28.32 52.7,29.97
VCC on TOP: 47.5,21.84 47.5,20.45 52.58,20.45 52.58,21.84
VCC on LAYER_2: 34.29,69.98 76.07,69.98 76.07,1.02 34.29,1.02
UNNAMED_2_ADMAX31732V2_I178_ALARM1 on TOP: 41.91,37.72 41.91,33.66 47.5,33.66 47.5,30.35 49.53,30.35 49.53,37.72
UNNAMED_2_ADMAX31732V2_I178_ALARM2 on TOP: 41.78,26.92 41.78,24 47.5,24 47.5,22.35 49.53,22.35 49.53,26.92
UNNAMED_2_CAP_I100_N1 on TOP: 53.34,65.02 53.34,61.09 55.24,61.09 55.24,65.02
UNNAMED_2_DIOLED_I82_P on TOP: 50.8,34.8 50.8,30.35 52.7,30.35 52.7,34.8
UNNAMED_2_DIOLED_I87_P on TOP: 50.67,27.05 50.67,22.35 52.58,22.35 52.58,27.05

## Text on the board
BOTTOM: SECONDARY SIDE | 08-074181 REV C
User.Comments: PCB : BOTTOM | PCB : TOP | TURRETS | FOR J1-J6, J9,J10: INSTALL SHUNTS ACROSS PIN1 AND PIN2. | FOR J7: INSTALL SHUNTS ACROSS PIN1 AND PIN2. | FOR J8: INSTALL SHUNTS ACROSS PIN5 AND PIN6.
TOP: 08-074181 REV C | FEB 2024
Ref Des/Silkscreen Top: CHANNEL1 | CHANNEL2 | CHANNEL3 | CHANNEL4 | DXP1 | GND1 | GND2 | DXP2 | DXP3 | GND3 | DXP4 | GND4 | WP | SDA | ADD | ALARM1 | ALARM2 | VCC | SCL | WP1 | GND | EN | EN1 | 4-CHANNEL REMOTE TEMPERATURE SENSOR | MAX31732EVKIT#
DIMENSION: CUTOUT | 0.84" | 0.875" | R=0.04" | CUTOUT DETAIL | 0.16" | 0.38"
PAGE_OUTLINE: FAB NOTES REVISION: 2ND NOVEMBER 2022 | 8.   IMPEDANCE REQUIREMENTS: IF NO STACKUP IS DEFINED, THE VENDOR IS ALLOWED TO ADJUST THE DIELECTRIC | 13.  PLATING SPECIFICATION: | 9.   FILLET OPTIONS TO ENHANCE RELIABILITY AT PAD JUNCTIONS WHERE SPACING PERMITS. | 10.  THIEVING: | 11.  LAYER TO LAYER REGISTRATION SHALL BE WITHIN 0.003 INCHES. | 12.  DRILL SIZES ARE FINISHED HOLE SIZES. ALL HOLES SHALL BE LOCATED WITHIN 0.005 INCHES DTP,UNLESS SPECIFIED. | 14.  SURFACE FINISH: | 15.  SOLDERMASK: | 1.   DIMENSIONS ARE IN INCHES (EXCEPT WHERE NOTED). | ALL DOCUMENTS & SPECIFICATIONS REFERRED TO BELOW SHOULD BE THE LATEST REVISIONS. | 2.  BOARD MATERIAL:(USE CHECKED ITEMS) | 3.   ALL LAMINATES & BONDING MATERIALS SHOULD BE SELECTED FROM IPC-4101 OR IPC-4103,(TG>170 DEGC TD>300 DEGC) | 4.   REFER TO IPC-6010 SERIES, CLASS 2 FOR FABRICATION. | 5.   REFER TO LAMINATION DIAGRAM FOR OVERALL BOARD THICKNESS, TOLERANCE APPLIES AFTER ALL LAMINATION AND PLATING | 6.   BOW & TWIST NOT TO EXCEED 0.0075 INCHES (0.75%) PER LINEAR INCH AND SHOULD BE MEASURED PER IPC-TM-650, METHOD 2.4.22. | 7.   ACCEPTABILITY PER ADI SPECIFICATION TST00115. | 16.  APPLY SILKSCREEN TO BOTH SIDES USING A NON-CONDUCTIVE, EPOXY BASED INK PER ARTWORK. | ( ) FILLETS ALLOWED | (X) FILLETS NOT ALLOWED | ( ) VENDOR MAY ADD THIEVING TO COMPENSATE FOR LOW COPPER DENSITY AREAS MAINTAINING A MINIMUM | (X) VENDOR MAY NOT ADD THIEVING TO COMPENSATE FOR LOW COPPER DENSITY AREAS. | (X) LPI | ( ) OTHER_________ | COLOR | ( ) GREEN | (X) OTHER____BLUE_____ | (X) WHITE | ( ) OTHER | HINDER PROPER SOLDER WICKING. BARREL RELIEF ON SOLDERMASK ALLOWED IN UNFILLED VIA IN PAD HOLES. | (X) REFER TO LAMINATION DIAGRAM FOR FINISHED COPPER WEIGHT/THICKNESS REQUIRMENTS | (X) IMMERSION GOLD (ENIG) 1.58-3.94 MICRO INCHES OVER 118-236 MICRO INCHES MIN. OF ELECTROLESS NICKEL PER IPC-4552 | ( ) OSP (ORGANIC SOLDERABILITY PRESERVATIVE) | ( ) IMMERSION SILVER | ( ) SOFT WIRE BONDABLE GOLD 30-50 MICRO INCHES OF SOFT WIRE | ( ) EDGE CONNECTOR FINGERS ARE TO BE PLATED WITH 100 MICRO-INCHES(.0001") OF LOW STRESS | THICKNESS & TRACE WIDTHS TO MEET THE IMPEDANCE REQUIREMENT. IF SPECIFIED, THE VENDOR MUST | TRACE WIDTH & SPACING THAT IMPACT THE REQUIREMENTS MUST HAVE WRITTEN APPROVAL FROM ADI. | MINIMUM BARREL PLATING OF 0.001 INCHES. PLATED HOLES SHALL NOT BE ROUGH OR IRREGULAR SO AS TO | SOLDERMASK OVER BARE COPPER OR BARE GOLD (BOTH SIDES) TO MEET IPC-SM-840. | IF PRESENT,DO NOT MODIFY SOLDERMASK DEFINED PADS (MASK OPENINGS LESS THAN COPPER PAD) WITHOUT APPROVAL. | MEET THE REQUIREMENTS LISTED IN THE IMPEDANCE TABLE. ANY ADJUSTMENT MADE TO THE DEFINED STACKUP, | PROCESSES. FINISHED THICKNESS MEASURED FROM TOP COPPER TO BOTTOM COPPER. | (X)  ISOLA 370HR OR S1000-2 OR IT180 OR EQUIVALENT | ( )  ISOLA-FR408HR OR EQUIVALENT | ( )  ISOLA IS410 | ( )  MEGTRON 6 | ( )  NELCO-4000-13 | ( )  ROGERS 4350B | ( ) ROGERS 3003 | ( ) ARLON 85N | ( ) EM370D | ( )  OTHER ________________________ | UL FLAMMABILITY RATING 94V-0. BOARD MATERIAL & CONSTRUCTION SHALL MEET THE REQUIREMENTS OF UL796/UL796F. | BONDABLE GOLD OVER 100-150 MICRO INCHES OF NICKEL | NICKEL UNDER 30 MICRO-INCHES (.0003') OF GOLD | 0.100 INCH CLEARANCE FROM ALL COPPER FEATURES, | THE STARTING COPPER WEIGHT/THICKNESS CAN VARY AS LONG AS THE FINISHED COPPER | WEIGHT/THICKNESS IS NOT LESS THAN THE SPECIFIED VALUE. | UNLESS OTHERWISE SPECIFIED | HOMOGENOUS MATERIALS IN THIS BOARD SHALL BE COMPLAINT WITH THE EU DIRECTIVE 2002/95/EC | WORKMANSHIP SHALL CONFORM TO IPC-A-600, CLASS 2. | 21.  INTENTIONAL SHORTS: | 17.  FINAL ELECTRICAL TEST TO BE PERFORMED USING PROVIDED IPC-D-356A NETLIST OR ODB++ FORMAT FILE. | 22.  PEMNUTS: | 23.  MANUFACTURER TO ETCH/STAMP WITH PERMANENT NON-CONDUCTIVE INK | ON SECONDARY SIDE UNLESS OTHERWISE SPECIFIED: | 18.  A TIME DOMAIN REFLECTOMETER REPORT (TDR) FOR EACH IMPEDANCE CONTROLLED LAYER & A CERTIFICATE | 19.  IF PRESENT, ALL BLIND/BURIED VIAS WITH AN ASPECT RATIO <1:1 TO BE PLATED SHUT WITH COPPER WHEN | 20.  FOR VIA FILL INFORMATION REFER TO DRILL CHART: | 25. PANELIZATION: | 27.  MINIMUM DESIGN LINE WIDTH IS .008 INCH. | 28.  MINIMUM DESIGN LINE SPACING IS .008 INCH. | IS ACCEPTABLE, ALL OTHER INSTANCES MUST BE REPORTED. | IF AN INTENTIONAL SHORT REPORT IS SUPPLIED AND DOES NOT MATCH THE FAB DATA THEN | THE PCB SHALL HAVE A VERIFICATION STAMP. | (X)  DRILLED VIAS LESS THAN OR EQUAL TO 0.012 INCHES SHALL BE PLUGGED AND COVERED WITH SOLDER MASK. | ( )  COPPER FILL ALL 0.XXXX INCHES DRILLED VIAS | ( ) PEMNUTS TO BE INSTALLED BY FABRICATOR | ( ) PEMNUTS NOT TO BE INSTALLED BY FABRICATOR | (X) NOT APPLICABLE | USED AS VIA-IN-PAD OR AS A STACKED VIA. BLIND/BURIED VIAS WITH AN ASPECT RATIO >1:1 TO BE FILLED | A. UL CODE-FLAMMABILITY RATING FOR THOSE APPROVED MATERIALS(IF APPLICABLE) | B. DATE CODE | C. LOT NUMBER | D. MANUFACTURER LOGO | BOARDS TO BE SHIPPED IN ARRAY AND KEPT INTACT | PANEL TO BE SUBJECTED TO CUSTOMERS APPROVAL | PANEL SOLDER PASTE STENCIL GERBER TO BE PROVIDED TO ANALOG | CAN'T BE PERFORMED BECAUSE THE TRACE LENGTH IS TOO SHORT ON THE OUTER LAYERS AT THE PIN ESCAPES | ADI APPROVAL IS REQUIRED. | OF COMPLIANCE SHALL BE PROVIDED BY VENDOR AT TIME OF SHIPMENT. INSTANCES WHERE TDR TESTING | WITH NON-CONDUCTIVE EPOXY. | ECR-119732 | 06MAR24 | TOOLING: | FINISH: | NOTES: | MATERIAL: | TESTING: | MISCELLANEOUS: | MAX31732EVKIT# | -074181 | C
User.18: 08-      -07 | L2-GND PLANE
User.19: 08-      -08 | L3-SIGNAL/GND
User.21: L5-SIGNAL/GND | 08-      -10
User.28: NO COMPONENTS SOLDERED ON SECONDARY SIDE.
User.44: 2
User.45: MICRO-USB | TO LAPTOP | 2 | FIGURE | SIZE | 6.0 | 12.0 | 40.0 | 45.0 | 63.0 | 80.0 | 185.0 | PLATED | NON-PLATED | FINISHED HOLES IN MILS | ALL UNITS ARE IN MILS | QTY | 4 | 333 | 24 | 16 | 17 | 400 | TOLERANCE/NOTES | TOTAL HOLES:
